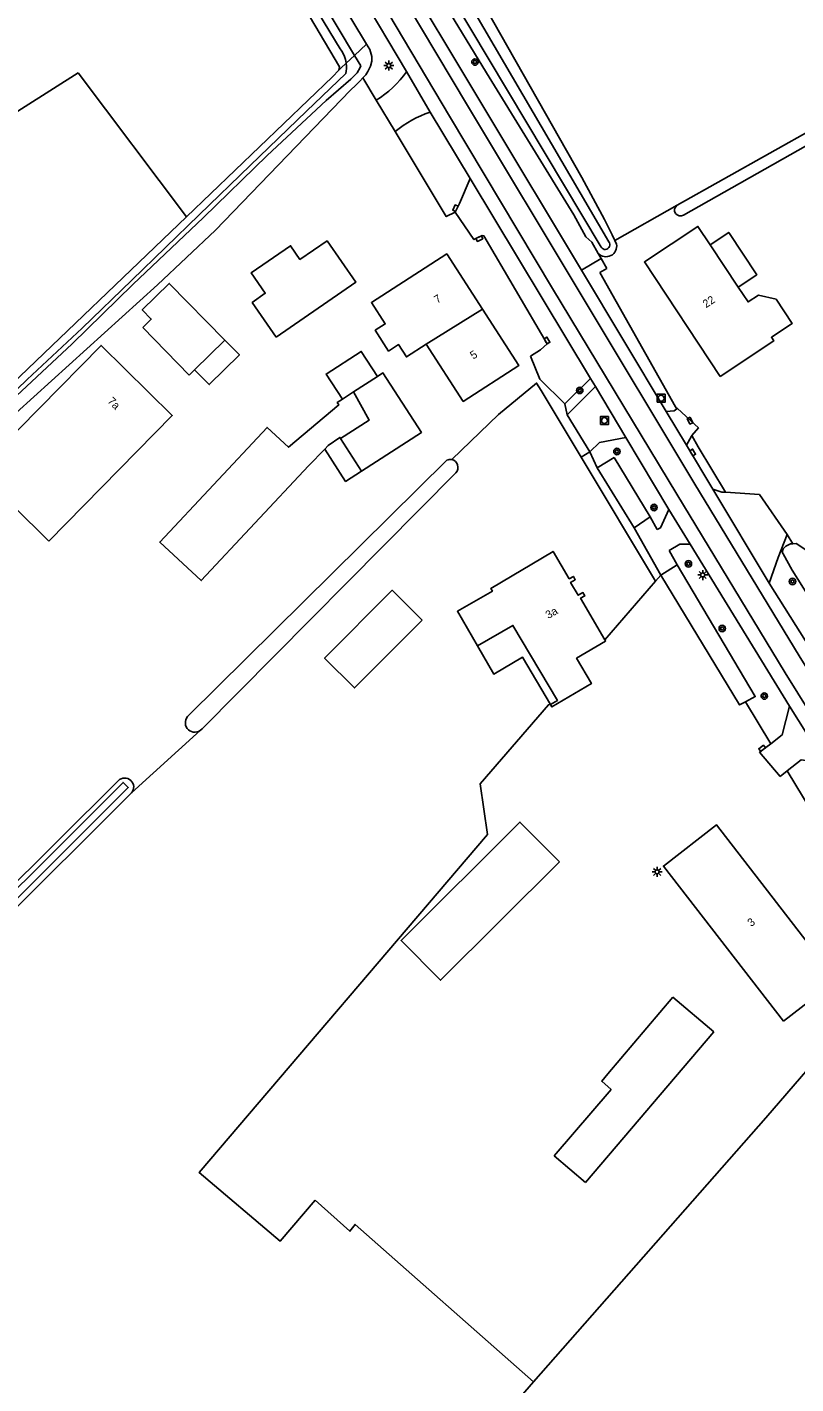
# Model space of a CAD drawing. Extents: x 137000 to 140001, y 403500 to 406000.
# Drawn here: x 139551.5 to 139647.6, y 403661 to 403830.5 of the extents above; entities that cross this region are included whole.
import ezdxf

# ---------------------------------------------------------------- set-up
doc = ezdxf.new("R2010")
doc.units = 0
for name, color, linetype in [('gg-afsc-erfafscheiding', 7, 'Continuous'), ('gg-afsc-hekwerk', 7, 'Continuous'), ('gg-anno-huisnummerreeks BGT', 7, 'Continuous'), ('gg-bbg-bijgebouw', 7, 'Continuous'), ('gg-bbg-gedigitaliseerde bebouwing', 7, 'Continuous'), ('gg-bbg-gedigitaliseerde bijgebouw', 7, 'Continuous'), ('gg-bbg-hoofdgebouw', 7, 'Continuous'), ('gg-bbg-luifel en loopbrug', 7, 'Continuous'), ('gg-bbg-open loods', 7, 'Continuous'), ('gg-bbg-tussenscheiding', 7, 'Continuous'), ('gg-knt-bronhoudergrens', 7, 'Continuous'), ('gg-knt-verharding', 7, 'Continuous'), ('gg-knt-verharding nz', 7, 'Continuous'), ('gg-kntw-bovenkant insteek waterloop', 7, 'Continuous'), ('gg-kntw-waterlijn', 7, 'Continuous'), ('gt-grn-groengrens', 7, 'Continuous'), ('gt-grn-groengrens NZ', 7, 'Continuous'), ('gt-grn-vlakafsluiter', 7, 'Continuous'), ('gt-grn-weggrens', 7, 'Continuous'), ('gt-symb-boom', 7, 'Continuous'), ('gt-symb-kolk', 7, 'Continuous'), ('gt-symb-kolk center center', 7, 'Continuous'), ('gt-symb-lichtmast', 7, 'Continuous'), ('gt-symb-rioolschacht', 7, 'Continuous')]:
    doc.layers.add(name, color=color, linetype=linetype)

# ---------------------------------------------------------------- blocks, each defined once
blk = doc.blocks.new('gt0-KOLK')
at = {"layer": 'gt-symb-kolk'}
blk.add_lwpolyline([(0, 0), (0.37, 0), (0.37, 0.4), (-0.38, 0.4), (-0.38, 0), (0, 0)], dxfattribs=at)
blk = doc.blocks.new('gt0-BOOM')
at = {"layer": 'gt-symb-boom'}
for radius in [0.4, 0.2]:
    blk.add_circle((0, 0), radius, dxfattribs=at)
blk = doc.blocks.new('gt0-LMAST')
at = {"layer": 'gt-symb-lichtmast'}
for p, q in [((-0.18, 0.17), (-0.45, 0.44)), ((-0.01, 0.25), (-0.01, 0.62)), ((0.17, 0.17), (0.44, 0.44)), ((-0.26, 0), (-0.63, 0)), ((-0.18, -0.18), (-0.45, -0.45)), ((-0.01, -0.25), (-0.01, -0.63)), ((0.44, -0.45), (0.17, -0.18)), ((0.24, 0), (0.62, 0))]:
    blk.add_line(p, q, dxfattribs=at)
blk.add_circle((-0.01, 0), 0.25, dxfattribs=at)
blk = doc.blocks.new('gt0-KOLKCC')
at = {"layer": 'gt-symb-kolk center center'}
blk.add_lwpolyline([(-0.38, 0.2), (0.38, 0.2), (0.38, -0.2), (-0.38, -0.2)], close=True, dxfattribs=at)
blk = doc.blocks.new('gt0-RS')
at = {"layer": 'gt-symb-rioolschacht'}
blk.add_lwpolyline([(-0.5, -0.5), (0.5, -0.5), (0.5, 0.5), (-0.5, 0.5)], close=True, dxfattribs=at)
blk.add_circle((0, 0), 0.375, dxfattribs=at)

msp = doc.modelspace()

# ---------------------------------------------------------------- linework, layer by layer
at = {"layer": 'gg-afsc-erfafscheiding'}
for p, q in [((139557.85, 403824.83), (139527.86, 403805.81)), ((139623.06, 403799.86), (139632.55, 403783.11)), ((139632.55, 403783.11), (139632.71, 403782.84))]:
    msp.add_line(p, q, dxfattribs=at)
msp.add_lwpolyline([(139614.8, 403661.28), (139643.81, 403694.25), (139656.94, 403709.43)], dxfattribs=at)
at = {"layer": 'gg-afsc-hekwerk'}
msp.add_line((139623.06, 403799.86), (139632.55, 403783.11), dxfattribs=at)
at = {"layer": 'gg-bbg-bijgebouw'}
for p, q in [((139593.29, 403775.07), (139590.66, 403779.14)), ((139632.21, 403709.33), (139637.31, 403704.99))]:
    msp.add_line(p, q, dxfattribs=at)
for points in [[(139582.6, 403791.79), (139579.63, 403796.11), (139581.24, 403797.29), (139579.47, 403799.82), (139584.41, 403803.22), (139585.59, 403801.5), (139588.98, 403803.83), (139592.55, 403798.65), (139582.6, 403791.79)], [(139590.89, 403784.05), (139588.86, 403787.19), (139593.24, 403790.02), (139595.27, 403786.88)], [(139593.29, 403775.07), (139600.76, 403779.89), (139595.95, 403787.32), (139595.27, 403786.88)], [(139588.7, 403777.8), (139586.66, 403775.71), (139573.24, 403761.37), (139568.06, 403766.19), (139581.48, 403780.52), (139584.16, 403778.03), (139590.43, 403783.33), (139590.24, 403783.63), (139590.89, 403784.05)], [(139588.7, 403777.8), (139589.13, 403778.24), (139590.58, 403779.26), (139590.66, 403779.14)], [(139600.88, 403756.43), (139597.12, 403760.17), (139588.67, 403751.7), (139592.41, 403747.96), (139600.88, 403756.43)], [(139618.02, 403726.25), (139613.08, 403731.21), (139598.23, 403716.4), (139603.17, 403711.44), (139618.02, 403726.25)], [(139624.51, 403697.79), (139623.32, 403698.81), (139624.08, 403699.74), (139632.21, 403709.33)]]:
    msp.add_lwpolyline(points, dxfattribs=at)
at = {"layer": 'gg-bbg-gedigitaliseerde bebouwing'}
msp.add_lwpolyline([(139554.19, 403766.31), (139569.63, 403781.99), (139560.72, 403790.76), (139545.28, 403775.08), (139554.19, 403766.31)], dxfattribs=at)
at = {"layer": 'gg-bbg-gedigitaliseerde bijgebouw'}
for p, q in [((139637.31, 403704.99), (139621.3, 403686.15)), ((139617.38, 403689.48), (139624.51, 403697.79)), ((139621.3, 403686.15), (139617.38, 403689.48))]:
    msp.add_line(p, q, dxfattribs=at)
at = {"layer": 'gg-bbg-hoofdgebouw'}
msp.add_line((139636.85, 403803.35), (139640.36, 403798.06), dxfattribs=at)
for points in [[(139636.85, 403803.35), (139635.33, 403805.64), (139628.64, 403801.2), (139638.12, 403786.88)], [(139601.37, 403790.93), (139598.9, 403789.33), (139597.91, 403790.86), (139596.67, 403790.06), (139594.99, 403792.65), (139596.24, 403793.45), (139594.52, 403796.12), (139603.94, 403802.2), (139608.39, 403795.31)], [(139640.36, 403798.06), (139641.6, 403796.19), (139642.89, 403797.05), (139645.1, 403796.53), (139647.11, 403793.49), (139644.52, 403791.78), (139644.82, 403791.33), (139638.12, 403786.88)], [(139608.39, 403795.31), (139612.94, 403788.25), (139605.99, 403783.77), (139601.37, 403790.93)], [(139623.7, 403753.99), (139620.66, 403759.17), (139621.19, 403759.47), (139620.96, 403759.88), (139620.37, 403759.54), (139619.42, 403761.14), (139620, 403761.49), (139619.78, 403761.9), (139619.24, 403761.6), (139617.22, 403765.02), (139609.46, 403760.4), (139609.65, 403760.07), (139605.27, 403757.54), (139607.77, 403753.22)], [(139616.9, 403745.9), (139617.76, 403746.4), (139612.2, 403755.78), (139607.77, 403753.22)], [(139616.9, 403745.9), (139617.09, 403745.59), (139622.02, 403748.51), (139620.17, 403751.67), (139623.8, 403753.81), (139623.7, 403753.99)], [(139646.03, 403706.32), (139631.02, 403725.7), (139637.66, 403730.85), (139652.67, 403711.47), (139646.03, 403706.32)]]:
    msp.add_lwpolyline(points, dxfattribs=at)
at = {"layer": 'gg-bbg-luifel en loopbrug'}
msp.add_line((139576.2, 403791.42), (139572.42, 403787.71), dxfattribs=at)
for points in [[(139636.85, 403803.35), (139639.18, 403804.89), (139642.69, 403799.6), (139640.36, 403798.06)], [(139572.42, 403787.71), (139574.24, 403785.86), (139578.02, 403789.57), (139576.2, 403791.42)], [(139588.7, 403777.8), (139591.29, 403773.78), (139593.29, 403775.07)], [(139607.77, 403753.22), (139609.81, 403749.7), (139613.4, 403751.82), (139616.9, 403745.9)]]:
    msp.add_lwpolyline(points, dxfattribs=at)
at = {"layer": 'gg-bbg-open loods'}
for p, q in [((139565.93, 403793), (139571.75, 403787.06)), ((139571.75, 403787.06), (139572.42, 403787.71))]:
    msp.add_line(p, q, dxfattribs=at)
msp.add_lwpolyline([(139565.93, 403793), (139567, 403794.05), (139565.87, 403795.2), (139569.25, 403798.52), (139576.2, 403791.42)], dxfattribs=at)
at = {"layer": 'gg-bbg-tussenscheiding'}
for p, q in [((139608.39, 403795.31), (139601.37, 403790.93)), ((139595.27, 403786.88), (139592.27, 403784.95)), ((139590.89, 403784.05), (139592.27, 403784.95))]:
    msp.add_line(p, q, dxfattribs=at)
msp.add_lwpolyline([(139590.66, 403779.14), (139594.23, 403781.42), (139592.27, 403784.95)], dxfattribs=at)
at = {"layer": 'gg-knt-bronhoudergrens'}
for p, q in [((139557.85, 403824.83), (139571.39, 403806.84)), ((139624.95, 403803.89), (139632.72, 403808.27)), ((139622.86, 403802.25), (139623.22, 403801.62)), ((139615.74, 403785.11), (139620.73, 403776.8)), ((139620.73, 403776.8), (139630.03, 403761.3)), ((139630.03, 403761.3), (139623.7, 403753.99)), ((139614.8, 403661.28), (139593.7, 403637.19))]:
    msp.add_line(p, q, dxfattribs=at)
for points in [[(139616.9, 403745.9), (139616.65, 403745.86), (139608.1, 403735.99), (139609.05, 403729.66)], [(139609.05, 403729.66), (139573, 403687.4), (139583.1, 403678.82), (139587.48, 403683.95)], [(139587.48, 403683.95), (139591.83, 403680.08), (139592.48, 403680.93), (139614.8, 403661.28)]]:
    msp.add_lwpolyline(points, dxfattribs=at)
at = {"layer": 'gg-knt-verharding'}
for p, q in [((139598.92, 403824.97), (139601.85, 403819.92)), ((139597.47, 403817.5), (139595.11, 403821.4)), ((139601.85, 403819.92), (139606.86, 403811.61)), ((139606.86, 403811.61), (139621.92, 403786.61)), ((139631.38, 403782.49), (139620.78, 403800.15)), ((139615.67, 403790.21), (139614.4, 403789.4)), ((139618.69, 403783.46), (139615.58, 403786.56)), ((139618.69, 403783.46), (139621.92, 403786.61)), ((139622.52, 403785.62), (139618.99, 403782.08)), ((139622.52, 403785.62), (139621.92, 403786.61)), ((139626.34, 403779.24), (139622.52, 403785.62)), ((139631.38, 403782.49), (139633.89, 403778.31)), ((139631.71, 403770.27), (139626.34, 403779.24)), ((139633.89, 403778.31), (139637.2, 403772.79)), ((139637.2, 403772.79), (139644.26, 403761.04)), ((139634.36, 403765.93), (139631.71, 403770.27)), ((139646.77, 403745.68), (139634.36, 403765.93)), ((139669.03, 403721.63), (139644.26, 403761.04)), ((139646.77, 403745.68), (139651.28, 403738.53)), ((139643.03, 403739.93), (139644.44, 403741)), ((139646.49, 403737.6), (139645.62, 403736.91))]:
    msp.add_line(p, q, dxfattribs=at)
for points in [[(139620.78, 403800.15), (139584.89, 403859.93), (139578.98, 403869.55), (139575.57, 403877.81), (139570, 403889), (139569.44, 403890.24)], [(139561.15, 403885.51), (139570.1, 403873.01), (139575.32, 403864.8), (139581.78, 403853.77), (139598.92, 403824.97)], [(139606.86, 403811.61), (139605.55, 403808.5), (139604.98, 403807.42)], [(139615.67, 403790.21), (139616.49, 403790.95), (139608.59, 403804.44), (139608.35, 403804.49), (139607.34, 403803.99), (139604.98, 403807.42)], [(139632.71, 403782.84), (139632.35, 403782.58), (139631.38, 403782.49)], [(139634.58, 403779.5), (139635.4, 403780.45), (139632.8, 403782.9), (139632.71, 403782.84)], [(139626.34, 403779.24), (139623.01, 403778.62), (139621.84, 403777.47)], [(139634.58, 403779.5), (139634.52, 403779.43), (139633.89, 403778.31)], [(139637.2, 403772.79), (139638.34, 403772.44), (139638.77, 403772.41)], [(139638.77, 403772.41), (139643.03, 403772.13), (139646.49, 403767.12)], [(139630.26, 403767.75), (139630.65, 403767.98), (139631.71, 403770.27)], [(139646.49, 403767.12), (139645.35, 403764.27), (139644.26, 403761.04)], [(139634.36, 403765.93), (139633.09, 403765.93), (139631.74, 403765.14)], [(139644.44, 403741), (139645.86, 403742.1), (139646.77, 403745.68)], [(139651.28, 403738.53), (139648.24, 403738.97), (139646.49, 403737.6)]]:
    msp.add_lwpolyline(points, dxfattribs=at)
for centre, radius, start, end in [((139588.6, 403832.19), 12.6, 301.1205, 325.011), ((139606.63, 403806.13), 14.6, 109.1318, 128.864)]:
    msp.add_arc(centre, radius, start, end, dxfattribs=at)
at = {"layer": 'gg-knt-verharding nz'}
for points in [[(139568.03, 403889.64), (139571.85, 403881.88), (139575.08, 403875.25), (139577.18, 403870.82), (139579.94, 403865.74), (139593.13, 403843.22), (139606.51, 403820.75), (139634.96, 403773.42), (139647.99, 403751.99), (139661.28, 403730.67), (139675.19, 403708.59), (139689.23, 403686.58), (139702.91, 403665.56), (139731.61, 403621.93), (139759.26, 403580.01), (139787.35, 403537.2), (139801.42, 403515.21), (139811.03, 403500)], [(139562.49, 403886.42), (139566.67, 403880.85), (139571.89, 403873.33), (139574.49, 403869.35), (139577.61, 403864.3), (139590.95, 403841.87), (139604.28, 403819.39), (139617.16, 403797.87), (139632.68, 403772.16), (139646.25, 403749.84), (139659.52, 403728.52), (139672.94, 403707.28), (139686.99, 403685.26), (139701.23, 403663.38), (139729.36, 403620.55), (139757.47, 403577.82), (139785.09, 403535.88), (139798.6, 403514.72), (139807.89, 403500)]]:
    msp.add_lwpolyline(points, dxfattribs=at)
at = {"layer": 'gg-kntw-bovenkant insteek waterloop'}
for p, q in [((139590.46, 403825.16), (139590.52, 403825.58)), ((139624.95, 403803.89), (139625.17, 403803.43)), ((139622.72, 403775.45), (139624.85, 403776.75)), ((139624.85, 403776.75), (139629.37, 403769.34)), ((139571.7, 403744.55), (139603.96, 403776.42)), ((139627.35, 403767.95), (139622.72, 403775.45)), ((139627.35, 403767.95), (139629.37, 403769.34)), ((139629.37, 403769.34), (139630.26, 403767.75)), ((139631.74, 403765.14), (139632.74, 403763.35)), ((139523.72, 403697.56), (139562.88, 403736.36)), ((139564.53, 403734.84), (139525.15, 403695.64))]:
    msp.add_line(p, q, dxfattribs=at)
for points in [[(139632.72, 403808.27), (139679.07, 403834.33), (139725.39, 403860.67), (139705.46, 403896.06), (139688.62, 403926.14), (139668.95, 403959.45)], [(139553.26, 403887.72), (139553.32, 403888.26), (139554.14, 403889.06), (139555.52, 403889.22), (139556.89, 403888.72), (139560.68, 403883.53), (139593.91, 403828.4)], [(139553.26, 403887.72), (139557.38, 403881.54), (139590.52, 403825.58)], [(139664.86, 403798.13), (139680.49, 403808.35), (139735.07, 403844.32), (139725.88, 403859.9), (139695.8, 403842.29), (139633.53, 403807.05)], [(139607.04, 403836.06), (139620.83, 403811.74), (139623.64, 403806.48), (139624.61, 403804.59), (139624.95, 403803.89)], [(139622.86, 403802.25), (139622.07, 403803.65), (139621.33, 403804.35), (139619.81, 403807.06), (139608.91, 403824.83), (139603.35, 403833.94)], [(139593.91, 403828.4), (139594.31, 403827.75), (139594.56, 403826.86), (139594.59, 403826.28), (139594.39, 403825.65), (139594.09, 403824.99), (139593.8, 403824.57), (139593.45, 403824.19)], [(139571.39, 403806.84), (139589.66, 403824.32), (139590.46, 403825.16)], [(139592.62, 403823.34), (139593.07, 403823.77), (139593.45, 403824.19)], [(139544.38, 403776.95), (139547.84, 403780.33), (139567.76, 403798.35), (139575.04, 403805.18), (139591.86, 403822.63), (139592.62, 403823.34)], [(139571.39, 403806.84), (139548.59, 403785.02), (139543.5, 403780.1)], [(139573.12, 403742.65), (139573.34, 403742.86), (139605.06, 403774.86)], [(139632.74, 403763.35), (139642.51, 403746.88), (139641.28, 403746.23)], [(139641.28, 403746.23), (139640.54, 403745.85), (139630.7, 403762.07)]]:
    msp.add_lwpolyline(points, dxfattribs=at)
for centre, radius, start, end in [((139633.14, 403807.67), 0.73, 125.3186, 302.4534), ((139623.84, 403803.19), 1.35, 223.8339, 10.0678), ((139604.37, 403775.54), 0.971, 78.7017, 114.8403), ((139604.37, 403775.54), 0.972, 315.1595, 78.6427), ((139572.44, 403743.62), 1.18, 128.6278, 304.9763), ((139563.67, 403735.57), 1.13, 319.5646, 135.0079)]:
    msp.add_arc(centre, radius, start, end, dxfattribs=at)
at = {"layer": 'gg-kntw-waterlijn'}
for p, q in [((139623.24, 403803.02), (139604.23, 403834.81)), ((139605.34, 403835.91), (139624.2, 403803.72)), ((139632.74, 403763.35), (139630.7, 403762.07))]:
    msp.add_line(p, q, dxfattribs=at)
for points in [[(139592.41, 403826.99), (139579.67, 403848.35), (139563.63, 403874.55), (139557.74, 403884.67), (139555.3, 403887.48), (139554.78, 403887.53), (139554.81, 403886.92), (139556.65, 403884.27), (139564.21, 403871.6), (139580.48, 403844.51), (139590.61, 403827.84)], [(139592.41, 403826.99), (139593.18, 403825.7), (139593.12, 403825.49), (139592.74, 403824.83), (139591.96, 403824.05)], [(139543.03, 403778.4), (139545.29, 403780.54), (139551.5, 403786.51), (139558.36, 403792.91), (139564.55, 403798.9), (139572.97, 403807.1), (139579.35, 403813.26), (139586.41, 403820.05), (139591.32, 403824.73)], [(139591.96, 403824.05), (139588.85, 403821.35), (139581.47, 403814.48), (139573.51, 403806.74), (139564.69, 403798.36), (139557.12, 403790.96), (139548.29, 403782.71), (139543.39, 403778.02)], [(139524.55, 403697.35), (139538.43, 403711.18), (139563.47, 403736.16), (139564.11, 403735.52), (139525.11, 403696.63), (139524.55, 403697.35)]]:
    msp.add_lwpolyline(points, dxfattribs=at)
for centre, radius, start, end in [((139587.64, 403825.53), 3.76, 7.4792, 37.9035), ((139587.65, 403825.53), 3.75, 347.6741, 7.4241), ((139623.74, 403803.35), 0.595, 213.6216, 38.596)]:
    msp.add_arc(centre, radius, start, end, dxfattribs=at)
at = {"layer": 'gt-grn-groengrens'}
for p, q in [((139595.11, 403821.4), (139593.45, 403824.19)), ((139618.69, 403783.46), (139618.99, 403782.08)), ((139621.84, 403777.47), (139620.73, 403776.8)), ((139622.72, 403775.45), (139621.84, 403777.47)), ((139647.18, 403765.99), (139646.49, 403767.12)), ((139641.28, 403746.23), (139644.44, 403741)), ((139656.35, 403721.26), (139646.49, 403737.6))]:
    msp.add_line(p, q, dxfattribs=at)
for points in [[(139604.98, 403807.42), (139603.88, 403806.87), (139597.47, 403817.5)], [(139638.77, 403772.41), (139635.35, 403778.09), (139634.58, 403779.5)], [(139647.18, 403765.99), (139647.62, 403766.03), (139649.06, 403765.05), (139662.85, 403741.6)]]:
    msp.add_lwpolyline(points, dxfattribs=at)
at = {"layer": 'gt-grn-groengrens NZ'}
msp.add_lwpolyline([(139661.37, 403740.08), (139647.12, 403762.7), (139645.98, 403764.71), (139645.87, 403764.95), (139645.98, 403765.36), (139646.31, 403765.7), (139646.9, 403765.96), (139647.18, 403765.99)], dxfattribs=at)
at = {"layer": 'gt-grn-vlakafsluiter'}
for p, q in [((139593.91, 403828.4), (139592.41, 403826.99)), ((139591.37, 403826.02), (139592.41, 403826.99)), ((139623.93, 403800.39), (139623.06, 403799.86)), ((139623.22, 403801.62), (139623.93, 403800.39)), ((139615.58, 403786.56), (139614.4, 403789.4)), ((139618.99, 403782.08), (139621.84, 403777.47)), ((139630.7, 403762.07), (139627.35, 403767.95)), ((139630.03, 403761.3), (139630.7, 403762.07)), ((139564.53, 403734.84), (139573.12, 403742.65)), ((139645.62, 403736.91), (139643.03, 403739.93))]:
    msp.add_line(p, q, dxfattribs=at)
for points in [[(139591.37, 403826.02), (139590.7, 403825.39), (139590.46, 403825.16)], [(139615.74, 403785.11), (139615.17, 403786.05), (139610.42, 403782.12), (139604.56, 403776.49)]]:
    msp.add_lwpolyline(points, dxfattribs=at)
at = {"layer": 'gt-grn-weggrens'}
msp.add_line((139623.22, 403801.62), (139620.78, 403800.15), dxfattribs=at)

# ---------------------------------------------------------------- block references
at = {"layer": 'gt-symb-boom'}
for p in [(139607.46, 403826.17), (139620.56, 403785.14), (139625.21, 403777.51), (139629.85, 403770.51), (139634.15, 403763.47), (139647.16, 403761.26), (139638.37, 403755.39), (139643.63, 403746.95)]:
    msp.add_blockref('gt0-BOOM', p, dxfattribs=at)
at = {"layer": 'gt-symb-kolk'}
for p, rotation in [((139605.2, 403807.83), 66.29807494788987), ((139607.92, 403804.28), -153.30141770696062), ((139616.3, 403791.27), -59.6535236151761), ((139634.51, 403777.28), -59.01686808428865), ((139643.48, 403740.27), 37.49774051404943)]:
    msp.add_blockref('gt0-KOLK', p, dxfattribs=dict(at, rotation=rotation))
at = {"layer": 'gt-symb-kolk center center', "rotation": -63.66231183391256}
msp.add_blockref('gt0-KOLKCC', (139634.35, 403781.36), dxfattribs=at)
at = {"layer": 'gt-symb-lichtmast'}
for p in [(139596.7, 403825.73), (139635.94, 403762.08), (139630.24, 403724.98)]:
    msp.add_blockref('gt0-LMAST', p, dxfattribs=at)
at = {"layer": 'gt-symb-rioolschacht'}
for p in [(139630.73, 403784.16), (139623.65, 403781.38)]:
    msp.add_blockref('gt0-RS', p, dxfattribs=at)

# ---------------------------------------------------------------- texts
at = {"layer": 'gg-anno-huisnummerreeks BGT'}
for s, rotation, p in [('7', 32.8, (139602.75, 403795.96)), ('22', 33.5, (139636.34, 403795.4)), ('5', 32.8, (139607.25, 403788.98)), ('7a', 315.5, (139561.46, 403783.71)), ('3a', 30.4, (139616.64, 403756.56)), ('3', 37.8, (139642, 403718.08))]:
    msp.add_text(s, height=1, rotation=rotation, dxfattribs=at).set_placement(p)

doc.saveas('drawing.dxf')
